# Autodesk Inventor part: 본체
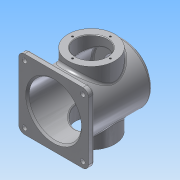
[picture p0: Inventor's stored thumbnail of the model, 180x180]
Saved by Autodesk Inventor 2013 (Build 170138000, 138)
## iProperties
Created: 2015-10
Part Number: 본체
Material: 알루미늄 6061
Document SubType Name: Modeling
Designer: Administrator
Density: 2.71 g/cm^3
Mass: 985.993 g
Surface Area: 1037.37 cm^2
Volume: 363.835 cm^3
Author: Administrator
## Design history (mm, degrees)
sketch "스케치1"
  geometry: C1 r 50 at (0, 0); 1 further point
  constraints: 1 centre point, 1 coincident
  dimensions: "d0" = 100 diameter of C1
extrude "돌출1" new body sketch "스케치1" stored distance "d1" = 110; taper "d2" = 0 deg
sketch "스케치2"
  geometry: C1 r 50 at (0, 0) reference; C2 r 40 at (0, 0)
  constraints: 1 centre point, 1 coincident
  dimensions: "d3" = 80 diameter of C2
extrude "돌출2" join sketch "스케치2" distance "d4" = 5; taper "d5" = 0 deg
sketch "스케치3"
  geometry: L1 (-60, 60)-(60, 60); L2 (60, 60)-(60, -60); L3 (60, -60)-(-60, -60); L4 (-60, -60)-(-60, 60); L5 (-60, 60)-(60, -60); L6 (60, 60)-(-60, -60); C1 r 50 at (0, 0) reference
  constraints: 12 end point, 2 midpoint, 2 parallel, 1 horizontal, 1 perpendicular
  dimensions: "d6" = 120 distance of L2.end L3.end; "d7" = 120 distance of L1.end L2.end
extrude "돌출3" join sketch "스케치3" distance "d8" = 10; taper "d9" = 0 deg
sketch "스케치4"
  geometry: C1 r 45 at (0, 0); 1 further point
  constraints: 1 centre point, 1 coincident
  dimensions: "d10" = 90 diameter of C1
extrude "돌출4" cut sketch "스케치4" distance "d11" = 112; taper "d12" = 0 deg
node "작업 평면1"
sketch "스케치6"
  geometry: C1 r 40 at (0, 0); 1 further point
  constraints: 1 centre point, 1 coincident
  dimensions: "d14" = 80 diameter of C1
extrude "돌출5" join sketch "스케치6" stored distance "d15" = 112; taper "d16" = 0 deg
sketch "스케치7"
  geometry: C1 r 40 at (0, 0) reference; C2 r 27 at (0, 0)
  constraints: 1 centre point, 1 coincident
  dimensions: "d17" = 54 diameter of C2
extrude "돌출6" cut sketch "스케치7" stored distance "d18" = 112; taper "d19" = 0 deg
sketch "스케치8"
  geometry: C1 r 27 at (0, 0) reference; 1 further point
  constraints: 1 vertical alignment
  dimensions: "d20" = 32.5 distance of C1.centre point (0, 32.5)
hole "구멍1" sketch "스케치8" at (0, 32.5) diameter "d21" = 3.242; stored, may be unused: countersink angle "d25" = 90 deg, drill point angle "d27" = 118 deg; dims "d22" = 8, "d23" = 4, "d24" = 2, "d26" = 10
fillet "모깎기1" dims "d31" = 5
sketch "스케치9"
  geometry: C1 r 40 at (0, 0) reference; C2 r 27 at (0, 0)
  constraints: 1 centre point, 1 coincident
  dimensions: "d32" = 54 diameter of C2
extrude "돌출7" cut sketch "스케치9" stored distance "d33" = 112; taper "d34" = 0 deg
sketch "스케치10"
  geometry: L1 (0, 0)-(22.981, 22.981); L2 (0, 0)-(32.5, 0); C1 r 40 at (0, 0) reference; 1 further point
  constraints: 4 end point, 1 coincident, 1 equal length, 1 horizontal
  dimensions: "d35" = 32.5 distance of L1.start L1.end; "d36" = 45 deg angle of L2 L1
hole "구멍2" sketch "스케치10" at (22.981, 22.981) diameter "d37" = 3.242; stored, may be unused: countersink angle "d41" = 90 deg, drill point angle "d43" = 118 deg; dims "d38" = 8, "d39" = 4, "d40" = 2, "d42" = 10
sketch "스케치11"
  geometry: L1 (-60, -60)-(60, -60) reference; C1 r 50 at (0, 0) reference; C2 r 4 at (50, -50)
  constraints: 1 centre point
  dimensions: "d47" = 8 diameter of C2; "d48" = 50 horizontal distance of C1.centre C2.centre; "d49" = 10 distance from line of L1 C2.centre
extrude "돌출8" cut sketch "스케치11" distance "d50" = 112; taper "d51" = 0 deg
fillet "모깎기2" dims "d58" = 5, "d59" = 3
chamfer "모따기1" distance "d60" = 3; stored, may be unused: second distance "d61" = 2, angle "d62" = 45 deg
fillet "모깎기3" dims "d63" = 3
fillet "모깎기4" dims "d64" = 10
fillet "모깎기5" dims "d65" = 3
chamfer "모따기2" distance "d66" = 1; stored, may be unused: second distance "d67" = 2, angle "d68" = 45 deg
node "작업 평면2"
sketch "스케치18"
  geometry: L1 (65, 50)-(65, -50) reference; 2 further points
  constraints: 1 horizontal alignment, 1 other
  dimensions: "d69" = 70 distance from line of L1 point (-5, 0)
feature "엠보싱1" sketch "스케치18" dims "d2" = 0, "d70" = 0.5, "d71" = 0
node "솔리드1"
pattern_circular "원형 패턴1" dims angle "d29" = 360 deg
mirror "대칭1"
pattern_circular "원형 패턴2" dims angle "d45" = 360 deg
pattern_linear "직사각형 패턴1" dims "d54" = 100
mirror "대칭2"
other parameters: "d13" = 62
